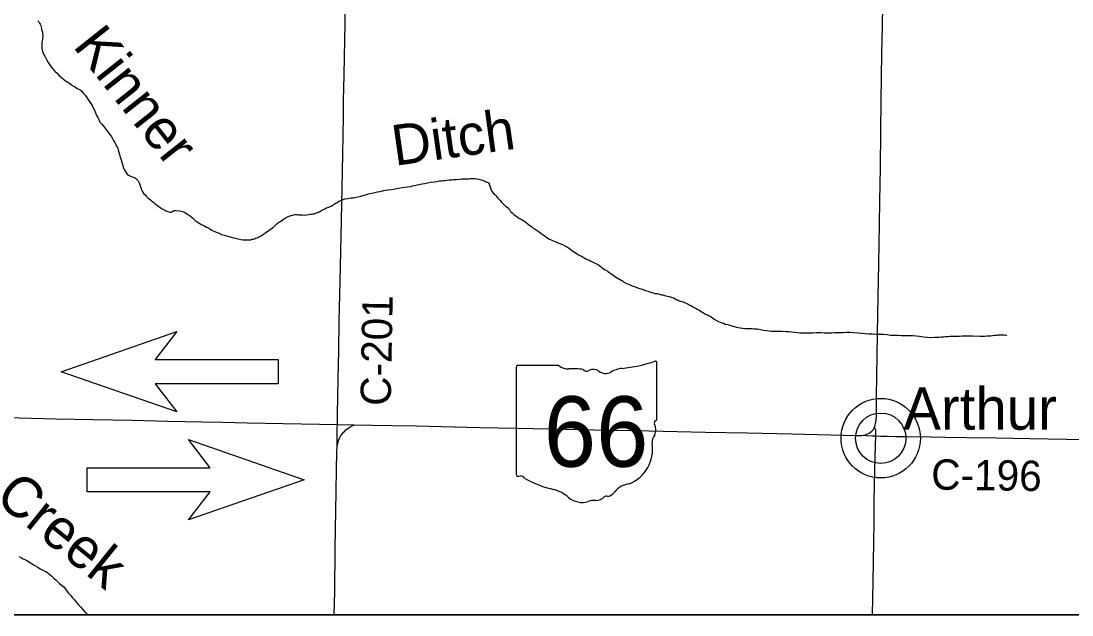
# Model space of a CAD drawing. Extents: x -483 to 680, y 0 to 440.
# Drawn here: x 243.8 to 342.2, y 55.9 to 111.5 of the extents above; entities that cross this region are included whole.
import ezdxf

# ---------------------------------------------------------------- set-up
doc = ezdxf.new("R2010")
doc.units = 0
for name, color, linetype in [('GM_X_County_Road', 7, 'Continuous'), ('GM_X_County_Road_Text', 7, 'Continuous'), ('GM_X_Minor_Lake_Text', 7, 'Continuous'), ('GM_X_Minor_River', 7, 'Continuous'), ('GM_X_State_Route', 7, 'Continuous'), ('GM_X_State_Shield', 7, 'Continuous'), ('GM_X_Unincorporated', 7, 'Continuous'), ('GM_X_Unincorporated_Location', 7, 'Continuous'), ('GM_X_Unincorporated_Text', 7, 'Continuous'), ('PM_P_Cells', 7, 'Continuous'), ('SH_Cut_Line', 7, 'Continuous'), ('SH_Text', 7, 'Continuous')]:
    doc.layers.add(name, color=color, linetype=linetype)

msp = doc.modelspace()

# ---------------------------------------------------------------- linework, layer by layer
at = {"layer": 'GM_X_County_Road'}
for points in [[(273.399, 73.76), (273.41, 74.745), (273.48, 78.087), (273.533, 80.653), (273.585, 83.452), (273.663, 87.183), (273.754, 91.381), (273.896, 97.444), (273.926, 99.154), (273.943, 100.709), (273.972, 102.73), (273.986, 104.13), (274.036, 106.462), (274.073, 108.171), (274.125, 111.216), (274.177, 114.235), (274.24, 117.656), (274.34, 121.854), (274.37, 124.047)], [(273.392, 71.718), (273.398, 73.46), (273.399, 73.76)], [(323.838, 72.7), (323.84, 72.96), (323.836, 73.07), (323.828, 73.2), (323.808, 73.298), (323.777, 73.369), (323.706, 73.498)], [(322.653, 72.766), (322.923, 72.741), (323.509, 72.708), (323.838, 72.7)], [(323.531, 55.95), (323.563, 57.582), (323.596, 58.98), (323.618, 61), (323.637, 62.708), (323.673, 64.57), (323.693, 66.59), (323.745, 69.54), (323.811, 71.861), (323.838, 72.636), (323.838, 72.7)], [(323.838, 72.7), (324.284, 72.689), (324.897, 72.675), (325.669, 72.648), (326.289, 72.636), (326.755, 72.633), (329.014, 72.607), (330.328, 72.571), (332.351, 72.546), (335.152, 72.509), (338.259, 72.452), (341.683, 72.409), (347.13, 72.331)]]:
    msp.add_lwpolyline(points, dxfattribs=at)
at = {"layer": 'GM_X_Minor_River'}
for points in [[(245.356, 111.551), (245.431, 111.437), (245.507, 111.323), (245.564, 111.228), (245.621, 111.113), (245.659, 110.98), (245.697, 110.809), (245.734, 110.638), (245.772, 110.486), (245.791, 110.333), (245.81, 110.219), (245.809, 110.048), (245.79, 109.915), (245.771, 109.782), (245.751, 109.668), (245.732, 109.535), (245.713, 109.383), (245.713, 109.212), (245.712, 109.079), (245.731, 108.965)], [(245.731, 108.965), (245.75, 108.813), (245.788, 108.661), (245.844, 108.509), (245.92, 108.375), (245.996, 108.223), (246.091, 108.052), (246.185, 107.861), (246.299, 107.652), (246.451, 107.442), (246.584, 107.233), (246.735, 107.061), (246.868, 106.89), (247.001, 106.756), (247.115, 106.661), (247.267, 106.49), (247.741, 106.07), (247.893, 105.956), (248.026, 105.879), (248.121, 105.841), (248.254, 105.745), (248.349, 105.669), (248.463, 105.574), (248.596, 105.459), (248.767, 105.402), (248.881, 105.326), (248.995, 105.249), (249.09, 105.192), (249.185, 105.154), (249.299, 105.096), (249.451, 104.963), (249.564, 104.848), (249.659, 104.715), (249.773, 104.582), (249.925, 104.372), (250.039, 104.201), (250.152, 104.01), (250.304, 103.801), (250.418, 103.61), (250.531, 103.401), (250.645, 103.173), (250.759, 102.944), (250.853, 102.697), (250.967, 102.506), (251.062, 102.297), (251.156, 102.05), (251.327, 101.878), (251.46, 101.707), (251.612, 101.516), (251.763, 101.307), (251.934, 101.116), (252.067, 100.926), (252.2, 100.735), (252.332, 100.545), (252.446, 100.335), (252.541, 100.145), (252.636, 99.974), (252.749, 99.764), (252.825, 99.612), (252.882, 99.441), (252.938, 99.251), (252.995, 99.079), (253.033, 98.889), (253.09, 98.718), (253.259, 98.128), (253.335, 97.862), (253.449, 97.576), (253.6, 97.367), (253.714, 97.196), (253.828, 97.1), (253.961, 97.024), (254.132, 96.985), (254.265, 96.928), (254.398, 96.889), (254.493, 96.832), (254.664, 96.68), (254.74, 96.565), (254.815, 96.432), (254.872, 96.299), (254.929, 96.147), (254.967, 96.013), (255.023, 95.842), (255.061, 95.728), (255.118, 95.614), (255.175, 95.5), (255.27, 95.366), (255.402, 95.252), (255.497, 95.138), (255.63, 95.004), (255.782, 94.89), (255.896, 94.794), (256.029, 94.68), (256.181, 94.565), (256.314, 94.451), (256.466, 94.336), (256.636, 94.203), (256.788, 94.089), (256.997, 93.936), (257.13, 93.879), (257.244, 93.821), (257.339, 93.764)], [(273.198, 94.44), (273.294, 94.497), (273.389, 94.535), (273.56, 94.668), (273.693, 94.724), (273.884, 94.8), (274.093, 94.875), (274.378, 94.931), (274.663, 94.969), (274.892, 94.987), (275.044, 95.005), (275.596, 95.137), (275.786, 95.212), (276.052, 95.269), (276.318, 95.344), (276.623, 95.419), (276.908, 95.475), (277.155, 95.532), (277.422, 95.588), (277.764, 95.663), (278.126, 95.719), (278.468, 95.775), (278.81, 95.831), (279.134, 95.887), (279.457, 95.943), (279.723, 95.98), (279.97, 96.018), (280.237, 96.055), (280.446, 96.111), (280.655, 96.149), (280.864, 96.186), (281.074, 96.224), (281.321, 96.28), (281.587, 96.317), (281.854, 96.374), (282.12, 96.449), (282.481, 96.486), (282.729, 96.523), (282.957, 96.56), (283.166, 96.579), (283.337, 96.597), (283.47, 96.616), (283.66, 96.634), (283.889, 96.653), (284.117, 96.671), (284.288, 96.69), (284.535, 96.708), (284.859, 96.726), (285.03, 96.745), (285.182, 96.763), (285.353, 96.763), (285.486, 96.762), (285.6, 96.762), (285.714, 96.762), (285.828, 96.78), (285.923, 96.78), (286.037, 96.78), (286.152, 96.779), (286.266, 96.779), (286.475, 96.759), (286.665, 96.74), (287.102, 96.606), (287.216, 96.548), (287.311, 96.491), (287.444, 96.433), (287.577, 96.376), (287.603, 96.36)], [(287.603, 96.36), (287.858, 95.58), (288.064, 95.368), (288.234, 95.233), (288.308, 95.118), (288.44, 94.945), (288.627, 94.752), (288.759, 94.617), (288.909, 94.463), (289.003, 94.348), (289.153, 94.213), (289.304, 94.116), (289.417, 94.019), (289.492, 93.904), (289.586, 93.808), (289.661, 93.674), (289.774, 93.577), (289.867, 93.481), (289.962, 93.404), (290.112, 93.287), (290.244, 93.191), (290.414, 93.093), (290.604, 92.996), (290.773, 92.879), (290.924, 92.782), (291.075, 92.685), (291.264, 92.53), (291.622, 92.26), (291.716, 92.182), (291.829, 92.105), (291.924, 92.046), (292.112, 91.911), (292.226, 91.852), (292.339, 91.774), (292.452, 91.659), (292.659, 91.542), (292.81, 91.426), (292.98, 91.31), (293.131, 91.193), (293.282, 91.115), (293.414, 91.038), (293.547, 90.979), (293.698, 90.92), (293.869, 90.86), (294.058, 90.782), (294.247, 90.722), (294.493, 90.605), (294.72, 90.487), (294.966, 90.351), (295.155, 90.234), (295.362, 90.061), (295.607, 89.905), (295.853, 89.75), (296.06, 89.614), (296.268, 89.516), (296.419, 89.419), (296.571, 89.341), (296.684, 89.282), (296.797, 89.224), (296.949, 89.165), (297.138, 89.067), (297.308, 88.988), (297.478, 88.891), (297.686, 88.793), (297.856, 88.696), (297.97, 88.637), (298.177, 88.463), (298.328, 88.347), (298.498, 88.25), (298.63, 88.172), (298.743, 88.095), (298.894, 87.998), (299.064, 87.881), (299.215, 87.765), (299.384, 87.611), (299.989, 87.279), (300.083, 87.24), (300.196, 87.105), (300.423, 87.007), (300.593, 86.929), (300.745, 86.87), (300.877, 86.811), (301.028, 86.733), (301.218, 86.673), (301.389, 86.614), (301.616, 86.535), (301.843, 86.475), (302.033, 86.415), (302.165, 86.337), (302.374, 86.277), (302.506, 86.238), (302.639, 86.198), (302.772, 86.158), (302.961, 86.098), (303.151, 86.039), (303.341, 86.017), (303.493, 85.996), (303.588, 85.976), (303.758, 85.916), (303.929, 85.895), (304.043, 85.855)], [(257.339, 93.764), (257.529, 93.687), (257.624, 93.668), (257.719, 93.649), (257.833, 93.648), (257.947, 93.686), (258.081, 93.781), (258.233, 93.799), (258.613, 93.76), (258.765, 93.741), (258.898, 93.702), (259.031, 93.664), (259.126, 93.607), (259.221, 93.549), (259.335, 93.454), (259.468, 93.378), (259.639, 93.263), (259.753, 93.168), (259.848, 93.091), (259.962, 92.996), (260.094, 92.863), (260.265, 92.748), (260.436, 92.633), (260.645, 92.5), (260.892, 92.385), (261.139, 92.251), (261.386, 92.137), (261.614, 91.965), (261.918, 91.831), (262.127, 91.735), (262.336, 91.659), (262.545, 91.563), (262.792, 91.486), (263.02, 91.41), (263.248, 91.352), (263.457, 91.294), (263.666, 91.237), (263.856, 91.198), (264.065, 91.141), (264.35, 91.083), (264.54, 91.063), (264.711, 91.044), (264.864, 91.043), (265.016, 91.043), (265.13, 91.042), (265.301, 91.061), (265.434, 91.099), (265.529, 91.117), (265.624, 91.155), (265.72, 91.212), (265.891, 91.249), (266.005, 91.306), (266.119, 91.363), (266.252, 91.438), (266.386, 91.514), (266.519, 91.609), (266.709, 91.722), (267.242, 92.101), (267.395, 92.214), (267.585, 92.404), (267.738, 92.536), (267.89, 92.669), (268.023, 92.745), (268.138, 92.839), (268.252, 92.934), (268.404, 93.029), (268.518, 93.086), (268.613, 93.142), (268.785, 93.218), (268.88, 93.255), (268.975, 93.293), (269.07, 93.331), (269.184, 93.369), (269.279, 93.387), (269.47, 93.406), (269.622, 93.424), (269.755, 93.405), (269.907, 93.386), (270.116, 93.385), (270.382, 93.365), (270.534, 93.384), (270.706, 93.421), (270.839, 93.44), (270.972, 93.459), (271.105, 93.477), (271.219, 93.496), (271.333, 93.534), (271.466, 93.571), (271.581, 93.628), (271.714, 93.685), (271.847, 93.76), (272.037, 93.855), (272.228, 93.949), (272.399, 94.044), (272.589, 94.119), (272.723, 94.176), (272.818, 94.214), (272.913, 94.27), (273.008, 94.308), (273.103, 94.384), (273.198, 94.44)], [(304.043, 85.855), (304.213, 85.815), (304.327, 85.775), (304.479, 85.735), (304.593, 85.715), (304.744, 85.656), (304.877, 85.616), (305.047, 85.519), (305.141, 85.479), (305.255, 85.421), (305.406, 85.343), (305.577, 85.302), (305.691, 85.282), (305.823, 85.242), (305.918, 85.202), (306.069, 85.124), (306.258, 85.027), (306.429, 84.948), (306.542, 84.909), (306.712, 84.792), (307.014, 84.617), (307.109, 84.578), (307.222, 84.5), (307.336, 84.461), (307.505, 84.326), (307.694, 84.209), (307.883, 84.092), (308.129, 83.994), (308.242, 83.935), (308.337, 83.896), (308.526, 83.76), (308.695, 83.625), (308.903, 83.489), (309.111, 83.41), (309.262, 83.332), (309.414, 83.292), (309.566, 83.252), (309.736, 83.174), (309.983, 83.113), (310.172, 83.054), (310.362, 83.013), (310.57, 82.934), (310.779, 82.874), (310.95, 82.834), (311.14, 82.812), (311.348, 82.771), (311.558, 82.769), (311.786, 82.746), (311.995, 82.763), (312.261, 82.74), (312.47, 82.737), (312.736, 82.714), (313.021, 82.672), (313.306, 82.611), (313.591, 82.57), (313.857, 82.547), (314.084, 82.506), (314.313, 82.503), (314.56, 82.518), (314.808, 82.515), (315.074, 82.511), (315.435, 82.487), (315.682, 82.465), (315.948, 82.442), (316.195, 82.401), (316.461, 82.378), (316.708, 82.356), (316.955, 82.333), (317.945, 82.358), (318.287, 82.372), (318.725, 82.366), (319.01, 82.343), (319.276, 82.34), (319.504, 82.336), (319.714, 82.353), (319.942, 82.369), (320.209, 82.384), (320.513, 82.38), (320.818, 82.394), (321.122, 82.409), (321.465, 82.405), (321.788, 82.381), (322.187, 82.338), (322.491, 82.315), (322.833, 82.291), (323.175, 82.267), (323.518, 82.262), (323.86, 82.239), (324.183, 82.234), (324.544, 82.21), (324.887, 82.187), (325.209, 82.144), (325.533, 82.121), (325.913, 82.116), (326.217, 82.111), (326.484, 82.108), (326.75, 82.104), (327.035, 82.1), (327.321, 82.096), (327.606, 82.073), (327.929, 82.031)], [(327.929, 82.031), (328.29, 81.988), (328.669, 81.945), (329.031, 81.921), (329.354, 81.935), (329.716, 81.949), (329.963, 81.965), (330.173, 81.981), (330.363, 81.998), (330.554, 82.014), (330.802, 82.049), (331.068, 82.045), (331.353, 82.041), (331.638, 82.037), (331.924, 82.052), (332.229, 82.067), (332.628, 82.061), (332.894, 82.058), (333.598, 82.048), (333.826, 82.045), (334.017, 82.043), (334.226, 82.059), (334.397, 82.056), (334.588, 82.073), (334.778, 82.089), (334.95, 82.125), (335.121, 82.141), (335.216, 82.14), (335.312, 82.158), (335.445, 82.156), (335.578, 82.154), (335.711, 82.152), (335.844, 82.151), (335.977, 82.13), (336.072, 82.128), (336.073, 82.147), (336.072, 82.128)], [(243.602, 61.418), (243.811, 61.303), (243.981, 61.208), (244.133, 61.131), (244.304, 61.036), (244.456, 60.94), (244.627, 60.845), (244.798, 60.749), (244.95, 60.654), (245.14, 60.539), (245.349, 60.406), (245.577, 60.272), (245.881, 60.1), (246.089, 60.004), (246.241, 59.909), (246.374, 59.813), (246.507, 59.699), (246.64, 59.566), (246.792, 59.451), (246.906, 59.337), (247.039, 59.222), (247.38, 58.879), (247.551, 58.746), (247.684, 58.631), (247.798, 58.536), (247.873, 58.441), (247.968, 58.345), (248.025, 58.25), (248.101, 58.155), (248.196, 58.022), (248.31, 57.888), (248.423, 57.755), (248.575, 57.584), (248.765, 57.355), (248.935, 57.145), (249.163, 56.898), (249.372, 56.688), (249.542, 56.478), (249.713, 56.288), (249.846, 56.136), (249.979, 55.983), (250.007, 55.95)]]:
    msp.add_lwpolyline(points, dxfattribs=at)
at = {"layer": 'GM_X_State_Route'}
for points in [[(274.99, 73.728), (276.623, 73.724), (278.489, 73.673), (280.823, 73.636), (283.155, 73.574), (286.733, 73.5), (290.155, 73.433), (296.376, 73.309), (297.465, 73.286), (299.331, 73.246), (302.598, 73.187), (305.242, 73.119), (307.886, 73.063), (311.775, 72.978), (315.974, 72.882), (322.04, 72.736), (322.349, 72.74), (322.504, 72.749), (322.653, 72.766), (322.803, 72.795), (322.949, 72.834), (323.089, 72.888), (323.223, 72.956), (323.347, 73.04), (323.459, 73.138), (323.588, 73.286), (323.663, 73.404), (323.706, 73.498), (323.736, 73.585), (323.781, 73.729), (323.816, 73.877), (323.858, 74.18), (323.887, 74.642), (323.916, 76.35), (324.027, 84.117), (324.12, 88.777), (324.186, 92.506), (324.226, 94.68), (324.274, 97.787), (324.309, 101.204), (324.354, 104), (324.417, 108.506), (324.464, 110.991), (324.53, 115.185)], [(240.084, 74.491), (247.076, 74.312), (250.496, 74.243), (254.225, 74.162), (257.489, 74.097), (260.752, 74.025), (262.617, 73.985), (264.948, 73.929), (273.399, 73.76), (274.99, 73.728)], [(273.106, 55.95), (273.15, 58.155), (273.198, 62.041), (273.224, 64.061), (273.25, 65.615), (273.331, 69.5), (273.352, 71.21), (273.384, 71.672), (273.392, 71.718), (273.432, 71.974), (273.512, 72.267), (273.631, 72.547), (273.706, 72.68), (273.789, 72.807), (273.88, 72.929), (273.98, 73.044), (274.088, 73.15), (274.21, 73.265), (274.328, 73.351), (274.463, 73.459), (274.614, 73.55), (274.791, 73.653), (274.99, 73.728)]]:
    msp.add_lwpolyline(points, dxfattribs=at)
at = {"layer": 'GM_X_State_Shield'}
for p, q in [((290.155, 79.118), (290.155, 69.112)), ((294.145, 79.29), (290.284, 79.29)), ((303.338, 74.304), (303.338, 79.538)), ((303.337, 74.305), (303.338, 74.304))]:
    msp.add_line(p, q, dxfattribs=at)
for centre, radius, start, end in [((290.306, 79.139), 0.153, 98.1301, 188.1301), ((295.065, 80.452), 1.481, 231.61951, 271.11188), ((295.556, 73.673), 5.318, 80.48669, 94.98827), ((296.763, 79.191), 0.427, 219.79206, 297.10237), ((297.391, 78.035), 0.889, 54.46668, 119.14113), ((298.537, 79.621), 1.069, 233.85621, 294.82819), ((300.425, 76.234), 2.813, 97.34618, 120.76885), ((298.642, 92.932), 13.981, 275.84447, 288.90645), ((303.192, 79.56), 0.147, 351.86209, 97.738), ((303.304, 73.92), 0.227, 107.94398, 210.33697), ((303.181, 74.284), 0.157, 289.60381, 7.73413), ((301.859, 73.258), 1.363, 340.03296, 23.64957), ((299.425, 71.448), 3.497, 292.30889, 8.98584), ((303.864, 72.113), 0.992, 136.8065, 186.92959), ((290.307, 69.09), 0.154, 171.95839, 258.30661), ((290.33, 70.114), 1.176, 267.33899, 280.60386), ((290.571, 68.535), 0.424, 29.74838, 93.27175), ((295.924, 77.525), 10.096, 240.41292, 257.1985), ((300.899, 66.303), 1.915, 94.40312, 142.57675), ((292.914, 64.617), 3.159, 47.18416, 75.83597), ((297.635, 67.736), 1.068, 268.77702, 315.54927), ((298.601, 66.767), 0.301, 65.75173, 132.64842), ((298.473, 68.142), 1.13, 282.87319, 323.27711), ((296.33, 68.485), 2.004, 230.70037, 286.29184), ((297.489, 65.026), 1.647, 85.69512, 111.20995)]:
    msp.add_arc(centre, radius, start, end, dxfattribs=at)
at = {"layer": 'GM_X_Unincorporated'}
for radius in [3.72, 2.358]:
    msp.add_circle((324.298, 72.488), radius, dxfattribs=at)
at = {"layer": 'GM_X_Unincorporated_Location'}
msp.add_line((324.298, 72.488), (324.298, 72.488), dxfattribs=at)
at = {"layer": 'PM_P_Cells'}
for p, q in [((247.54, 78.714), (258.379, 82.477)), ((258.379, 82.477), (256.347, 79.843)), ((256.347, 79.843), (267.863, 79.843)), ((267.863, 79.843), (267.863, 77.585)), ((258.379, 74.951), (247.54, 78.714)), ((267.863, 77.585), (256.347, 77.585)), ((256.347, 77.585), (258.379, 74.951)), ((259.461, 72.363), (270.3, 68.6)), ((261.493, 69.729), (259.461, 72.363)), ((249.977, 67.471), (249.977, 69.729)), ((249.977, 69.729), (261.493, 69.729)), ((270.3, 68.6), (259.461, 64.837)), ((261.493, 67.471), (249.977, 67.471)), ((259.461, 64.837), (261.493, 67.471))]:
    msp.add_line(p, q, dxfattribs=at)
at = {"layer": 'SH_Cut_Line'}
msp.add_lwpolyline([(45.608, 55.95), (373.798, 55.95)], dxfattribs=at)
at = {"layer": 'SH_Text'}
msp.add_lwpolyline([(45.608, 395.95), (385.608, 395.95), (385.608, 55.95), (45.608, 55.95)], close=True, dxfattribs=at)

# ---------------------------------------------------------------- texts
at = {"layer": 'GM_X_County_Road_Text'}
for s, rotation, p in [('C-201', 88.89838, (278.395, 75.496)), ('C-196', 359.17308, (329.013, 67.686))]:
    msp.add_text(s, height=2.8409, rotation=rotation, dxfattribs=at).set_placement(p)
at = {"layer": 'GM_X_Minor_Lake_Text'}
for s, height, rotation, p in [('Kinner', 3.7896, 308.34129, (248.548, 109.168)), ('Ditch', 3.7898, 8.04646, (278.784, 97.967)), ('Creek', 3.7889, 321.04133, (241.187, 66.697))]:
    msp.add_text(s, height=height, rotation=rotation, dxfattribs=at).set_placement(p)
at = {"layer": 'GM_X_State_Shield'}
msp.add_text('66', height=6.5918, dxfattribs=at).set_placement((292.731, 69.818))
at = {"layer": 'GM_X_Unincorporated_Text'}
msp.add_text('Arthur', height=3.9489, rotation=0.00001, dxfattribs=at).set_placement((326.418, 73.285))

doc.saveas('drawing.dxf')
